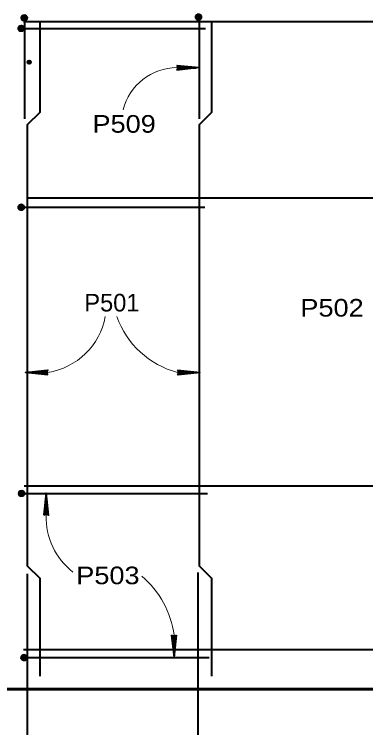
# Model space of a CAD drawing. Extents: x 6.34 to 9.53, y -1.46 to 0.53.
# Drawn here: x 6.7323 to 6.8984, y -0.7412 to -0.4039 of the extents above; entities that cross this region are included whole.
import ezdxf

# ---------------------------------------------------------------- set-up
doc = ezdxf.new("R2010")
doc.units = 0
doc.header["$LTSCALE"] = 0.0033
doc.header["$PDMODE"] = 32
doc.header["$PDSIZE"] = 0.00165
doc.layers.add('1', color=7, linetype='Continuous', lineweight=40)

msp = doc.modelspace()

# ---------------------------------------------------------------- linework, layer by layer
at = {"layer": '1'}
for p, q in [((6.736083, -0.4065), (6.736417, -0.404583)), ((6.73625, -0.406583), (6.736583, -0.404583)), ((6.736333, -0.4045), (6.737833, -0.404583)), ((6.736333, -0.406583), (6.736667, -0.404583)), ((6.736333, -0.404667), (6.737833, -0.40475)), ((6.736417, -0.406583), (6.736833, -0.404583)), ((6.7365, -0.406583), (6.736917, -0.404583)), ((6.736667, -0.406583), (6.737, -0.404667)), ((6.73675, -0.406667), (6.737083, -0.404667)), ((6.736833, -0.406667), (6.73725, -0.404667)), ((6.818417, -0.406083), (6.81875, -0.404167)), ((6.818583, -0.406167), (6.818917, -0.404167)), ((6.818667, -0.404083), (6.820167, -0.404167)), ((6.818667, -0.406167), (6.819, -0.404167)), ((6.818667, -0.40425), (6.820167, -0.404333)), ((6.818667, -0.404333), (6.820167, -0.404417)), ((6.818667, -0.404417), (6.820167, -0.4045)), ((6.818667, -0.4045), (6.820167, -0.404583)), ((6.818667, -0.404583), (6.820167, -0.404667)), ((6.818667, -0.404667), (6.820167, -0.40475)), ((6.81875, -0.406167), (6.819167, -0.404167)), ((6.818833, -0.406167), (6.81925, -0.404167)), ((6.819, -0.406167), (6.819333, -0.40425)), ((6.819083, -0.40625), (6.819417, -0.40425)), ((6.819167, -0.40625), (6.819583, -0.40425)), ((6.81925, -0.40625), (6.819667, -0.404333)), ((6.819333, -0.40625), (6.81975, -0.404333)), ((6.8195, -0.406333), (6.819917, -0.404333)), ((6.81975, -0.406333), (6.820083, -0.404333)), ((6.819833, -0.406333), (6.820167, -0.404417)), ((6.819917, -0.406333), (6.82025, -0.404417)), ((6.82, -0.406417), (6.820333, -0.404417)), ((6.73625, -0.405583), (6.73775, -0.405667)), ((6.73625, -0.405667), (6.73775, -0.40575)), ((6.73625, -0.40575), (6.73775, -0.405833)), ((6.73625, -0.405833), (6.73775, -0.405917)), ((6.73625, -0.405917), (6.73775, -0.406)), ((6.73625, -0.406), (6.73775, -0.406083)), ((6.73625, -0.406083), (6.73775, -0.406167)), ((6.73625, -0.40625), (6.73775, -0.406333)), ((6.73625, -0.406333), (6.73775, -0.406417)), ((6.73625, -0.406417), (6.73775, -0.4065)), ((6.73625, -0.4065), (6.73775, -0.406583)), ((6.73625, -0.406583), (6.73775, -0.406667)), ((6.736333, -0.40475), (6.737833, -0.404833)), ((6.736333, -0.404833), (6.737833, -0.404917)), ((6.736333, -0.404917), (6.737833, -0.405)), ((6.736333, -0.405), (6.737833, -0.405083)), ((6.736333, -0.405083), (6.737833, -0.405167)), ((6.736333, -0.405167), (6.737833, -0.40525)), ((6.736333, -0.405167), (6.737833, -0.40525)), ((6.736333, -0.40525), (6.737833, -0.405417)), ((6.736333, -0.405417), (6.737833, -0.405583)), ((6.736917, -0.406667), (6.737333, -0.40475)), ((6.737, -0.406667), (6.737417, -0.40475)), ((6.737083, -0.407083), (6.737083, -0.453417)), ((6.737167, -0.40675), (6.737583, -0.40475)), ((6.737417, -0.40675), (6.73775, -0.40475)), ((6.7375, -0.40675), (6.737833, -0.404833)), ((6.737583, -0.40675), (6.737917, -0.404833)), ((6.737667, -0.406833), (6.738, -0.404833)), ((6.818583, -0.405167), (6.820083, -0.40525)), ((6.818583, -0.40525), (6.820083, -0.405333)), ((6.818583, -0.405333), (6.820083, -0.405417)), ((6.818583, -0.405417), (6.820083, -0.4055)), ((6.818583, -0.4055), (6.820083, -0.405583)), ((6.818583, -0.405583), (6.820083, -0.405667)), ((6.818583, -0.405667), (6.820083, -0.40575)), ((6.818583, -0.405833), (6.820083, -0.405917)), ((6.818583, -0.405917), (6.820083, -0.406)), ((6.818583, -0.406), (6.820083, -0.406083)), ((6.818583, -0.406083), (6.820083, -0.406167)), ((6.818583, -0.406167), (6.820083, -0.40625)), ((6.818667, -0.40475), (6.820167, -0.404833)), ((6.818667, -0.40475), (6.820167, -0.404833)), ((6.818667, -0.404833), (6.820167, -0.405)), ((6.818667, -0.405), (6.820167, -0.405167)), ((6.819667, -0.407083), (6.819667, -0.453417)), ((6.734417, -0.411333), (6.7345, -0.409833)), ((6.7365, -0.411167), (6.7345, -0.41075)), ((6.7365, -0.41125), (6.7345, -0.410833)), ((6.7365, -0.411333), (6.7345, -0.411)), ((6.7365, -0.411417), (6.7345, -0.411083)), ((6.736417, -0.411583), (6.7345, -0.41125)), ((6.734583, -0.411333), (6.734667, -0.409833)), ((6.736583, -0.410833), (6.734583, -0.410417)), ((6.736583, -0.410917), (6.734583, -0.410583)), ((6.7365, -0.411), (6.734583, -0.410667)), ((6.734667, -0.411333), (6.73475, -0.409833)), ((6.736667, -0.41025), (6.734667, -0.409917)), ((6.736667, -0.4105), (6.734667, -0.410083)), ((6.736583, -0.410667), (6.734667, -0.41025)), ((6.736583, -0.41075), (6.734667, -0.410333)), ((6.73675, -0.41), (6.73475, -0.409667)), ((6.736667, -0.410083), (6.73475, -0.40975)), ((6.73475, -0.411333), (6.734833, -0.409833)), ((6.736667, -0.410167), (6.73475, -0.409833)), ((6.734833, -0.411333), (6.734917, -0.409833)), ((6.734917, -0.411333), (6.735, -0.409833)), ((6.735, -0.411333), (6.735083, -0.409833)), ((6.735083, -0.411333), (6.735167, -0.409833)), ((6.735083, -0.411333), (6.735167, -0.409833)), ((6.735167, -0.411333), (6.735333, -0.409833)), ((6.735333, -0.411333), (6.7355, -0.409833)), ((6.7355, -0.411417), (6.735583, -0.409917)), ((6.735583, -0.411417), (6.735667, -0.409917)), ((6.735667, -0.411417), (6.73575, -0.409917)), ((6.73575, -0.411417), (6.735833, -0.409917)), ((6.735833, -0.411417), (6.735917, -0.409917)), ((6.735917, -0.411417), (6.736, -0.409917)), ((6.736, -0.411417), (6.736083, -0.409917)), ((6.736167, -0.411417), (6.73625, -0.409917)), ((6.73625, -0.411417), (6.736333, -0.409917)), ((6.736333, -0.411417), (6.736417, -0.409917)), ((6.736417, -0.411417), (6.7365, -0.409917)), ((6.7365, -0.411417), (6.736583, -0.409917)), ((6.737, -0.410583), (6.822667, -0.410583)), ((6.738333, -0.490667), (6.962, -0.490667)), ((6.734417, -0.495917), (6.7345, -0.494417)), ((6.7365, -0.49575), (6.7345, -0.495333)), ((6.7365, -0.495833), (6.7345, -0.495417)), ((6.7365, -0.495917), (6.7345, -0.495583)), ((6.7365, -0.496), (6.7345, -0.495667)), ((6.734583, -0.495917), (6.734667, -0.494417)), ((6.736583, -0.495417), (6.734583, -0.495)), ((6.736583, -0.4955), (6.734583, -0.495167)), ((6.7365, -0.495583), (6.734583, -0.49525)), ((6.734667, -0.495917), (6.73475, -0.494417)), ((6.736667, -0.494833), (6.734667, -0.4945)), ((6.736667, -0.495083), (6.734667, -0.494667)), ((6.736583, -0.49525), (6.734667, -0.494833)), ((6.736583, -0.495333), (6.734667, -0.494917)), ((6.73675, -0.494583), (6.73475, -0.49425)), ((6.736667, -0.494667), (6.73475, -0.494333)), ((6.73475, -0.495917), (6.734833, -0.494417)), ((6.736667, -0.49475), (6.73475, -0.494417)), ((6.734833, -0.495917), (6.734917, -0.494417)), ((6.734917, -0.495917), (6.735, -0.494417)), ((6.735, -0.495917), (6.735083, -0.494417)), ((6.735083, -0.495917), (6.735167, -0.494417)), ((6.735083, -0.495917), (6.735167, -0.494417)), ((6.735167, -0.495917), (6.735333, -0.494417)), ((6.735333, -0.495917), (6.7355, -0.494417)), ((6.7355, -0.496), (6.735583, -0.4945)), ((6.735583, -0.496), (6.735667, -0.4945)), ((6.735667, -0.496), (6.73575, -0.4945)), ((6.73575, -0.496), (6.735833, -0.4945)), ((6.735833, -0.496), (6.735917, -0.4945)), ((6.735917, -0.496), (6.736, -0.4945)), ((6.736, -0.496), (6.736083, -0.4945)), ((6.736167, -0.496), (6.73625, -0.4945)), ((6.73625, -0.496), (6.736333, -0.4945)), ((6.736333, -0.496), (6.736417, -0.4945)), ((6.736417, -0.496), (6.7365, -0.4945)), ((6.7365, -0.496), (6.736583, -0.4945)), ((6.737, -0.495167), (6.822333, -0.495167)), ((6.736417, -0.496167), (6.7345, -0.495833)), ((6.734583, -0.631167), (6.734667, -0.629667)), ((6.736667, -0.631), (6.734667, -0.630583)), ((6.73475, -0.631167), (6.734833, -0.629667)), ((6.73675, -0.630667), (6.73475, -0.63025)), ((6.73675, -0.63075), (6.73475, -0.630417)), ((6.736667, -0.630833), (6.73475, -0.6305)), ((6.734833, -0.631167), (6.734917, -0.629667)), ((6.736833, -0.630083), (6.734833, -0.62975)), ((6.736833, -0.630333), (6.734833, -0.629917)), ((6.73675, -0.6305), (6.734833, -0.630083)), ((6.73675, -0.630583), (6.734833, -0.630167)), ((6.736917, -0.629833), (6.734917, -0.6295)), ((6.736833, -0.629917), (6.734917, -0.629583)), ((6.734917, -0.631167), (6.735, -0.629667)), ((6.736833, -0.63), (6.734917, -0.629667)), ((6.735, -0.631167), (6.735083, -0.629667)), ((6.735083, -0.631167), (6.735167, -0.629667)), ((6.735167, -0.631167), (6.73525, -0.629667)), ((6.73525, -0.631167), (6.735333, -0.629667)), ((6.73525, -0.631167), (6.735333, -0.629667)), ((6.735333, -0.631167), (6.7355, -0.629667)), ((6.7355, -0.631167), (6.735667, -0.629667)), ((6.735667, -0.63125), (6.73575, -0.62975)), ((6.73575, -0.63125), (6.735833, -0.62975)), ((6.735833, -0.63125), (6.735917, -0.62975)), ((6.735917, -0.63125), (6.736, -0.62975)), ((6.736, -0.63125), (6.736083, -0.62975)), ((6.736083, -0.63125), (6.736167, -0.62975)), ((6.736167, -0.63125), (6.73625, -0.62975)), ((6.736333, -0.63125), (6.736417, -0.62975)), ((6.736417, -0.63125), (6.7365, -0.62975)), ((6.7365, -0.63125), (6.736583, -0.62975)), ((6.736583, -0.63125), (6.736667, -0.62975)), ((6.736667, -0.63125), (6.73675, -0.62975)), ((6.737167, -0.630417), (6.823667, -0.630417)), ((6.736667, -0.631083), (6.734667, -0.630667)), ((6.736667, -0.631167), (6.734667, -0.630833)), ((6.736667, -0.63125), (6.734667, -0.630917)), ((6.736583, -0.631417), (6.734667, -0.631083)), ((6.738417, -0.6685), (6.738417, -0.780333)), ((6.819083, -0.667833), (6.819083, -0.780833)), ((6.73575, -0.70875), (6.735833, -0.70725)), ((6.737833, -0.708583), (6.735833, -0.708167)), ((6.735917, -0.70875), (6.736, -0.70725)), ((6.737917, -0.70825), (6.735917, -0.707833)), ((6.737917, -0.708333), (6.735917, -0.708)), ((6.737833, -0.708417), (6.735917, -0.708083)), ((6.736, -0.70875), (6.736083, -0.70725)), ((6.738, -0.707667), (6.736, -0.707333)), ((6.738, -0.707917), (6.736, -0.7075)), ((6.737917, -0.708083), (6.736, -0.707667)), ((6.737917, -0.708167), (6.736, -0.70775)), ((6.738083, -0.707417), (6.736083, -0.707083)), ((6.738, -0.7075), (6.736083, -0.707167)), ((6.736083, -0.70875), (6.736167, -0.70725)), ((6.738, -0.707583), (6.736083, -0.70725)), ((6.736167, -0.70875), (6.73625, -0.70725)), ((6.73625, -0.70875), (6.736333, -0.70725)), ((6.736333, -0.70875), (6.736417, -0.70725)), ((6.736417, -0.70875), (6.7365, -0.70725)), ((6.736417, -0.70875), (6.7365, -0.70725)), ((6.7365, -0.70875), (6.736667, -0.70725)), ((6.736667, -0.70875), (6.736833, -0.70725)), ((6.736833, -0.708833), (6.736917, -0.707333)), ((6.736917, -0.708833), (6.737, -0.707333)), ((6.737, -0.708833), (6.737083, -0.707333)), ((6.737083, -0.708833), (6.737167, -0.707333)), ((6.737167, -0.708833), (6.73725, -0.707333)), ((6.73725, -0.708833), (6.737333, -0.707333)), ((6.737333, -0.708833), (6.737417, -0.707333)), ((6.7375, -0.708833), (6.737583, -0.707333)), ((6.737583, -0.708833), (6.737667, -0.707333)), ((6.737667, -0.708833), (6.73775, -0.707333)), ((6.73775, -0.708833), (6.737833, -0.707333)), ((6.737833, -0.708833), (6.737917, -0.707333)), ((6.738333, -0.708), (6.824333, -0.708)), ((6.737833, -0.708667), (6.735833, -0.70825)), ((6.737833, -0.70875), (6.735833, -0.708417)), ((6.737833, -0.708833), (6.735833, -0.7085)), ((6.73775, -0.709), (6.735833, -0.708667))]:
    msp.add_line(p, q, dxfattribs=at)
at = {"layer": '1', "lineweight": 35}
for p, q in [((6.809417, -0.428167), (6.81725, -0.429083)), ((6.809417, -0.428167), (6.81725, -0.429083)), ((6.809417, -0.42825), (6.81725, -0.429083)), ((6.809167, -0.429167), (6.81975, -0.429167)), ((6.809333, -0.429833), (6.816667, -0.429083)), ((6.809417, -0.428333), (6.81725, -0.429167)), ((6.809417, -0.428333), (6.81725, -0.429333)), ((6.809417, -0.43), (6.81675, -0.429167)), ((6.809417, -0.430083), (6.81675, -0.429333)), ((6.809417, -0.43025), (6.81675, -0.429417)), ((6.748167, -0.57325), (6.737583, -0.57325)), ((6.747917, -0.574083), (6.740083, -0.573083)), ((6.747917, -0.574083), (6.740083, -0.57325)), ((6.747917, -0.572167), (6.740583, -0.573)), ((6.747917, -0.572333), (6.740583, -0.573083)), ((6.747917, -0.572417), (6.740583, -0.57325)), ((6.748, -0.572583), (6.740667, -0.573333)), ((6.8095, -0.57325), (6.820083, -0.57325)), ((6.809667, -0.573917), (6.817, -0.573167)), ((6.80975, -0.57225), (6.817583, -0.573167)), ((6.80975, -0.57225), (6.817583, -0.573167)), ((6.80975, -0.572333), (6.817583, -0.573167)), ((6.80975, -0.572417), (6.817583, -0.57325)), ((6.80975, -0.572417), (6.817583, -0.573417)), ((6.80975, -0.574083), (6.817083, -0.57325)), ((6.747917, -0.57425), (6.740083, -0.573333)), ((6.747917, -0.57425), (6.740083, -0.573333)), ((6.747917, -0.574167), (6.740083, -0.573333)), ((6.80975, -0.574167), (6.817083, -0.573417)), ((6.80975, -0.574333), (6.817083, -0.5735)), ((6.747333, -0.64075), (6.747333, -0.630167)), ((6.746333, -0.6405), (6.74725, -0.632667)), ((6.746333, -0.6405), (6.74725, -0.632667)), ((6.746417, -0.6405), (6.74725, -0.632667)), ((6.7465, -0.6405), (6.747333, -0.632667)), ((6.7465, -0.6405), (6.7475, -0.632667)), ((6.748, -0.640583), (6.74725, -0.63325)), ((6.748167, -0.6405), (6.747333, -0.633167)), ((6.74825, -0.6405), (6.7475, -0.633167)), ((6.748417, -0.6405), (6.747583, -0.633167)), ((6.80675, -0.697667), (6.807583, -0.705)), ((6.806917, -0.697667), (6.807667, -0.705)), ((6.807, -0.697667), (6.807833, -0.705)), ((6.807167, -0.697583), (6.807917, -0.704917)), ((6.808667, -0.697667), (6.807667, -0.7055)), ((6.807833, -0.697417), (6.807833, -0.708)), ((6.808667, -0.697667), (6.807833, -0.7055)), ((6.808833, -0.697667), (6.807917, -0.7055)), ((6.808833, -0.697667), (6.807917, -0.7055)), ((6.80875, -0.697667), (6.807917, -0.7055))]:
    msp.add_line(p, q, dxfattribs=at)
at = {"layer": '1'}
for points in [[(6.737083, -0.407), (6.73675, -0.404417), (6.73625, -0.40675), (6.737333, -0.404417), (6.73775, -0.406833), (6.738083, -0.404833), (6.736, -0.404833), (6.738333, -0.40575), (6.73575, -0.4055), (6.738083, -0.4065), (6.73575, -0.406167), (6.738333, -0.405333), (6.736583, -0.406917), (6.736417, -0.4045), (6.73825, -0.406167), (6.735833, -0.405083), (6.73625, -0.40675), (6.73775, -0.406833), (6.738333, -0.40575), (6.738083, -0.404833), (6.737333, -0.404417), (6.736417, -0.4045), (6.735833, -0.405083), (6.736917, -0.40575), (6.737833, -0.404583), (6.738083, -0.4065), (6.736917, -0.40575), (6.736417, -0.406833), (6.73575, -0.405833), (6.736833, -0.40575), (6.738083, -0.404917), (6.736833, -0.406917), (6.7365, -0.405583), (6.736, -0.404833)], [(6.819417, -0.406583), (6.819083, -0.404), (6.818583, -0.406333), (6.819667, -0.404), (6.820083, -0.406417), (6.820417, -0.404417), (6.818333, -0.404417), (6.820667, -0.405333), (6.818083, -0.405083), (6.820417, -0.406083), (6.818083, -0.40575), (6.820667, -0.404917), (6.818917, -0.4065), (6.81875, -0.404083), (6.820583, -0.40575), (6.818167, -0.404667), (6.818583, -0.406333), (6.820083, -0.406417), (6.820667, -0.405333), (6.820417, -0.404417), (6.819667, -0.404), (6.81875, -0.404083), (6.818167, -0.404667), (6.81925, -0.405333), (6.820167, -0.404167), (6.820417, -0.406083), (6.81925, -0.405333), (6.81875, -0.406417), (6.818083, -0.405417), (6.819167, -0.405333), (6.820417, -0.4045), (6.819167, -0.4065), (6.818833, -0.405167), (6.818333, -0.404417)], [(6.736667, -0.407333), (6.962167, -0.407333), (7.290333, -0.407333)], [(6.744333, -0.407), (6.744333, -0.450333), (6.738417, -0.45625), (6.738417, -0.664583), (6.744333, -0.6705), (6.744333, -0.71675)], [(6.825583, -0.407), (6.825583, -0.450333), (6.819667, -0.45625), (6.819667, -0.664583), (6.825583, -0.6705), (6.825583, -0.71675)], [(6.736917, -0.410583), (6.734333, -0.410917), (6.736667, -0.411417), (6.734333, -0.410333), (6.73675, -0.409917), (6.73475, -0.409583), (6.73475, -0.411667), (6.735667, -0.409333), (6.735417, -0.411917), (6.736417, -0.409583), (6.736083, -0.411917), (6.73525, -0.409333), (6.736833, -0.411083), (6.734417, -0.41125), (6.736083, -0.409417), (6.735, -0.411833), (6.736667, -0.411417), (6.73675, -0.409917), (6.735667, -0.409333), (6.73475, -0.409583), (6.734333, -0.410333), (6.734417, -0.41125), (6.735, -0.411833), (6.735667, -0.41075), (6.7345, -0.409833), (6.736417, -0.409583), (6.735667, -0.41075), (6.73675, -0.41125), (6.73575, -0.411917), (6.735667, -0.410833), (6.734833, -0.409583), (6.736833, -0.410833), (6.7355, -0.411167), (6.73475, -0.411667)], [(6.736917, -0.495167), (6.734333, -0.4955), (6.736667, -0.496), (6.734333, -0.494917), (6.73675, -0.4945), (6.73475, -0.494167), (6.73475, -0.49625), (6.735667, -0.493917), (6.735417, -0.4965), (6.736417, -0.494167), (6.736083, -0.4965), (6.73525, -0.493917), (6.736833, -0.495667), (6.734417, -0.495833), (6.736083, -0.494), (6.735, -0.496417), (6.736667, -0.496), (6.73675, -0.4945), (6.735667, -0.493917), (6.73475, -0.494167), (6.734333, -0.494917), (6.734417, -0.495833), (6.735, -0.496417), (6.735667, -0.495333), (6.7345, -0.494417), (6.736417, -0.494167), (6.735667, -0.495333), (6.73675, -0.495833), (6.73575, -0.4965), (6.735667, -0.495417), (6.734833, -0.494167), (6.736833, -0.495417), (6.7355, -0.49575), (6.73475, -0.49625)], [(6.737, -0.626833), (6.962167, -0.626833), (7.287917, -0.626833)], [(6.737083, -0.630417), (6.7345, -0.63075), (6.736833, -0.63125), (6.7345, -0.630167), (6.736917, -0.62975), (6.734917, -0.629417), (6.734917, -0.6315), (6.735833, -0.629167), (6.735583, -0.63175), (6.736583, -0.629417), (6.73625, -0.63175), (6.735417, -0.629167), (6.737, -0.630917), (6.734583, -0.631083), (6.73625, -0.62925), (6.735167, -0.631667), (6.736833, -0.63125), (6.736917, -0.62975), (6.735833, -0.629167), (6.734917, -0.629417), (6.7345, -0.630167), (6.734583, -0.631083), (6.735167, -0.631667), (6.735833, -0.630583), (6.734667, -0.629667), (6.736583, -0.629417), (6.735833, -0.630583), (6.736917, -0.631083), (6.735917, -0.63175), (6.735833, -0.630667), (6.735, -0.629417), (6.737, -0.630667), (6.735667, -0.631), (6.734917, -0.6315)], [(6.736583, -0.704167), (6.962167, -0.704167), (7.2875, -0.704167)], [(6.73825, -0.708), (6.735667, -0.708333), (6.738, -0.708833), (6.735667, -0.70775), (6.738083, -0.707333), (6.736083, -0.707), (6.736083, -0.709083), (6.737, -0.70675), (6.73675, -0.709333), (6.73775, -0.707), (6.737417, -0.709333), (6.736583, -0.70675), (6.738167, -0.7085), (6.73575, -0.708667), (6.737417, -0.706833), (6.736333, -0.70925), (6.738, -0.708833), (6.738083, -0.707333), (6.737, -0.70675), (6.736083, -0.707), (6.735667, -0.70775), (6.73575, -0.708667), (6.736333, -0.70925), (6.737, -0.708167), (6.735833, -0.70725), (6.73775, -0.707), (6.737, -0.708167), (6.738083, -0.708667), (6.737083, -0.709333), (6.737, -0.70825), (6.736167, -0.707), (6.738167, -0.70825), (6.736833, -0.708583), (6.736083, -0.709083)]]:
    msp.add_lwpolyline(points, dxfattribs=at)
at = {"layer": '1', "lineweight": 35}
for points in [[(6.809167, -0.428083), (6.81975, -0.429167), (6.809167, -0.430333), (6.80975, -0.429167)], [(6.809917, -0.429083), (6.814583, -0.429), (6.814583, -0.429083), (6.813667, -0.429083), (6.809917, -0.429), (6.812917, -0.428917), (6.80975, -0.428833), (6.812, -0.42875), (6.80975, -0.428667), (6.81325, -0.428917), (6.817917, -0.429083), (6.817, -0.429333), (6.81825, -0.429333), (6.809917, -0.429333), (6.812333, -0.4295), (6.80975, -0.4295), (6.815083, -0.429083), (6.80975, -0.42975)], [(6.748167, -0.574333), (6.737583, -0.57325), (6.748167, -0.572083), (6.747583, -0.57325)], [(6.747417, -0.573333), (6.74275, -0.573417), (6.74275, -0.573333), (6.743667, -0.573333), (6.747417, -0.573417), (6.744417, -0.5735), (6.747583, -0.573583), (6.745333, -0.573667), (6.747583, -0.57375), (6.744083, -0.5735), (6.739417, -0.573333), (6.740333, -0.573083), (6.739083, -0.573083), (6.747417, -0.573083), (6.745, -0.572917), (6.747583, -0.572917), (6.74225, -0.573333), (6.747583, -0.572667)], [(6.8095, -0.572167), (6.820083, -0.57325), (6.8095, -0.574417), (6.810083, -0.57325)], [(6.81025, -0.573167), (6.814917, -0.573083), (6.814917, -0.573167), (6.814, -0.573167), (6.81025, -0.573083), (6.81325, -0.573), (6.810083, -0.572917), (6.812333, -0.572833), (6.810083, -0.57275), (6.813583, -0.573), (6.81825, -0.573167), (6.817333, -0.573417), (6.818583, -0.573417), (6.81025, -0.573417), (6.812667, -0.573583), (6.810083, -0.573583), (6.815417, -0.573167), (6.810083, -0.573833)], [(6.74625, -0.64075), (6.747333, -0.630167), (6.7485, -0.64075), (6.747333, -0.640167)], [(6.74725, -0.64), (6.747167, -0.635333), (6.74725, -0.635333), (6.74725, -0.63625), (6.747167, -0.64), (6.747083, -0.637), (6.747, -0.640167), (6.746917, -0.637917), (6.746833, -0.640167), (6.747083, -0.636667), (6.74725, -0.632), (6.7475, -0.632917), (6.7475, -0.631667), (6.7475, -0.64), (6.747667, -0.637583), (6.747667, -0.640167), (6.74725, -0.634833), (6.747917, -0.640167)], [(6.808917, -0.697417), (6.807833, -0.708), (6.806667, -0.697417), (6.807833, -0.698)], [(6.807917, -0.698167), (6.808, -0.702833), (6.807917, -0.702833), (6.807917, -0.701917), (6.808, -0.698167), (6.808083, -0.701167), (6.808167, -0.698), (6.80825, -0.70025), (6.808333, -0.698), (6.808083, -0.7015), (6.807917, -0.706167), (6.807667, -0.70525), (6.807667, -0.7065), (6.807667, -0.698167), (6.8075, -0.700583), (6.8075, -0.698), (6.807917, -0.703333), (6.80725, -0.698)]]:
    msp.add_lwpolyline(points, close=True, dxfattribs=at)
for points in [[(6.809917, -0.429083), (6.8095, -0.428333), (6.80975, -0.428583), (6.809917, -0.428917), (6.810167, -0.428833), (6.81, -0.4285), (6.809833, -0.42925), (6.809667, -0.42975), (6.809417, -0.430167)], [(6.747417, -0.573333), (6.747833, -0.574083), (6.747583, -0.573833), (6.747417, -0.5735), (6.747167, -0.573583), (6.747333, -0.573917), (6.7475, -0.573167), (6.747667, -0.572667), (6.747917, -0.57225)], [(6.81025, -0.573167), (6.809833, -0.572417), (6.810083, -0.572667), (6.81025, -0.573), (6.8105, -0.572917), (6.810333, -0.572583), (6.810167, -0.573333), (6.81, -0.573833), (6.80975, -0.57425)], [(6.74725, -0.64), (6.7465, -0.640417), (6.74675, -0.640167), (6.747083, -0.64), (6.747, -0.63975), (6.746667, -0.639917), (6.747417, -0.640083), (6.747917, -0.64025), (6.748333, -0.6405)], [(6.807917, -0.698167), (6.808667, -0.69775), (6.808417, -0.698), (6.808083, -0.698167), (6.808167, -0.698417), (6.8085, -0.69825), (6.80775, -0.698083), (6.80725, -0.697917), (6.806833, -0.697667)]]:
    msp.add_lwpolyline(points, dxfattribs=at)
at = {"layer": '1', "lineweight": 60}
msp.add_lwpolyline([(6.718917, -0.722917), (6.962083, -0.722917), (7.30225, -0.722917)], dxfattribs=at)
at = {"layer": '1'}
for centre in [(6.737033, -0.405667), (6.819367, -0.40525), (6.735583, -0.410633), (6.735583, -0.495217), (6.73575, -0.630467), (6.736917, -0.70805)]:
    msp.add_circle(centre, 0.00132, dxfattribs=at)
at = {"layer": '1', "lineweight": 13}
for centre, radius, start, end in [((6.809262, -0.455465), 0.026298, 90.20866, 165.95631), ((6.742944, -0.540702), 0.032964, 279.1157, 349.28048), ((6.820098, -0.532987), 0.041634, 199.42455, 255.25359), ((6.78053, -0.641486), 0.033205, 178.7301, 231.80918), ((6.764446, -0.703094), 0.043757, 7.45528, 49.98176)]:
    msp.add_arc(centre, radius, start, end, dxfattribs=at)
at = {"layer": '1'}
msp.add_point((6.739333, -0.426583), dxfattribs=at)

# ---------------------------------------------------------------- texts
at = {"layer": '1', "width": 1.15}
for s, p in [('P509', (6.76925, -0.459917)), ('P502', (6.8675, -0.546833)), ('P503', (6.761583, -0.673333))]:
    msp.add_text(s, height=0.008334, dxfattribs=at).set_placement(p)
at = {"layer": '1'}
msp.add_text('P501', height=0.008334, dxfattribs=at).set_placement((6.765417, -0.544417))

doc.saveas('drawing.dxf')
